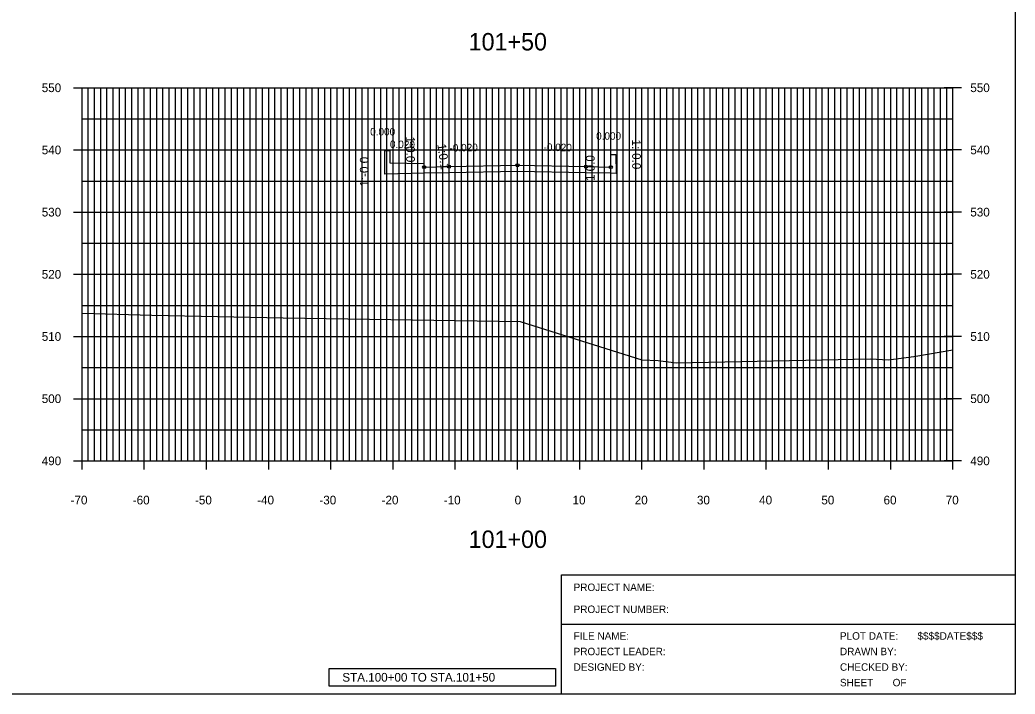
# Model space of a CAD drawing. Extents: x 1509063 to 1512863, y 401160 to 402918.
# Drawn here: x 1511262.7 to 1511422.7, y 402252.1 to 402360.5 of the extents above; entities that cross this region are included whole.
import ezdxf

# ---------------------------------------------------------------- set-up
doc = ezdxf.new("R2010")
doc.units = 0
for name, color, linetype in [('NBL1', 7, 'Continuous'), ('PET_P', 7, 'Continuous'), ('PRC', 7, 'Continuous'), ('PSP_P', 7, 'Continuous'), ('XAX_P', 7, 'Continuous'), ('XAXTIC_P', 7, 'Continuous'), ('XAXTXT_P_T', 7, 'Continuous'), ('XFRAME_P', 7, 'Continuous'), ('XGL_P', 7, 'Continuous'), ('XSL1_P', 7, 'Continuous'), ('XSL1_P_T', 7, 'Continuous'), ('XSL3_P', 7, 'Continuous'), ('XSLOG', 7, 'Continuous')]:
    doc.layers.add(name, color=color, linetype=linetype)

msp = doc.modelspace()

# ---------------------------------------------------------------- linework, layer by layer
at = {"layer": 'NBL1'}
for p, q in [((1511349.81, 402271.25), (1511422.73, 402271.25)), ((1511349.81, 402252.08), (1511349.81, 402271.25)), ((1511349.81, 402263.33), (1511422.73, 402263.33))]:
    msp.add_line(p, q, dxfattribs=at)
msp.add_lwpolyline([(1511422.73, 402252.08), (1511102.73, 402252.08), (1511102.73, 402462.08), (1511422.73, 402462.08)], close=True, dxfattribs=at)
at = {"layer": 'PET_P'}
for centre in [(1511331.73, 402336.9), (1511353.73, 402336.9)]:
    msp.add_circle(centre, 0.25, dxfattribs=at)
at = {"layer": 'PRC'}
msp.add_circle((1511342.73, 402337.12), 0.25, dxfattribs=at)
at = {"layer": 'PSP_P'}
for centre in [(1511327.73, 402336.82), (1511357.73, 402336.82)]:
    msp.add_circle(centre, 0.25, dxfattribs=at)
at = {"layer": 'XAX_P'}
for p, q in [((1511272.73, 402289.58), (1511272.73, 402349.58)), ((1511342.73, 402289.58), (1511342.73, 402349.58)), ((1511412.73, 402289.58), (1511412.73, 402349.58)), ((1511272.73, 402289.58), (1511412.73, 402289.58))]:
    msp.add_line(p, q, dxfattribs=at)
at = {"layer": 'XAXTIC_P'}
for p, q in [((1511271.33, 402349.58), (1511274.13, 402349.58)), ((1511341.33, 402349.58), (1511344.13, 402349.58)), ((1511414.13, 402349.58), (1511411.33, 402349.58)), ((1511271.33, 402339.58), (1511274.13, 402339.58)), ((1511341.33, 402339.58), (1511344.13, 402339.58)), ((1511414.13, 402339.58), (1511411.33, 402339.58)), ((1511271.33, 402329.58), (1511274.13, 402329.58)), ((1511341.33, 402329.58), (1511344.13, 402329.58)), ((1511414.13, 402329.58), (1511411.33, 402329.58)), ((1511271.33, 402319.58), (1511274.13, 402319.58)), ((1511341.33, 402319.58), (1511344.13, 402319.58)), ((1511414.13, 402319.58), (1511411.33, 402319.58)), ((1511271.33, 402309.58), (1511274.13, 402309.58)), ((1511341.33, 402309.58), (1511344.13, 402309.58)), ((1511414.13, 402309.58), (1511411.33, 402309.58)), ((1511271.33, 402299.58), (1511274.13, 402299.58)), ((1511341.33, 402299.58), (1511344.13, 402299.58)), ((1511414.13, 402299.58), (1511411.33, 402299.58)), ((1511272.73, 402288.18), (1511272.73, 402290.98)), ((1511282.73, 402288.18), (1511282.73, 402290.98)), ((1511292.73, 402288.18), (1511292.73, 402290.98)), ((1511302.73, 402288.18), (1511302.73, 402290.98)), ((1511312.73, 402288.18), (1511312.73, 402290.98)), ((1511322.73, 402288.18), (1511322.73, 402290.98)), ((1511332.73, 402288.18), (1511332.73, 402290.98)), ((1511342.73, 402288.18), (1511342.73, 402290.98)), ((1511352.73, 402288.18), (1511352.73, 402290.98)), ((1511362.73, 402288.18), (1511362.73, 402290.98)), ((1511372.73, 402288.18), (1511372.73, 402290.98)), ((1511382.73, 402288.18), (1511382.73, 402290.98)), ((1511392.73, 402288.18), (1511392.73, 402290.98)), ((1511402.73, 402288.18), (1511402.73, 402290.98)), ((1511412.73, 402288.18), (1511412.73, 402290.98)), ((1511271.33, 402289.58), (1511274.13, 402289.58)), ((1511341.33, 402289.58), (1511344.13, 402289.58)), ((1511414.13, 402289.58), (1511411.33, 402289.58))]:
    msp.add_line(p, q, dxfattribs=at)
at = {"layer": 'XFRAME_P'}
msp.add_lwpolyline([(1511312.43, 402256.18), (1511348.83, 402256.18), (1511348.83, 402253.38), (1511312.43, 402253.38)], close=True, dxfattribs=at)
at = {"layer": 'XGL_P'}
for p, q in [((1511272.73, 402349.58), (1511412.73, 402349.58)), ((1511272.73, 402289.58), (1511272.73, 402349.58)), ((1511273.73, 402289.58), (1511273.73, 402349.58)), ((1511274.73, 402289.58), (1511274.73, 402349.58)), ((1511275.73, 402289.58), (1511275.73, 402349.58)), ((1511276.73, 402289.58), (1511276.73, 402349.58)), ((1511277.73, 402289.58), (1511277.73, 402349.58)), ((1511278.73, 402289.58), (1511278.73, 402349.58)), ((1511279.73, 402289.58), (1511279.73, 402349.58)), ((1511280.73, 402289.58), (1511280.73, 402349.58)), ((1511281.73, 402289.58), (1511281.73, 402349.58)), ((1511282.73, 402289.58), (1511282.73, 402349.58)), ((1511283.73, 402289.58), (1511283.73, 402349.58)), ((1511284.73, 402289.58), (1511284.73, 402349.58)), ((1511285.73, 402289.58), (1511285.73, 402349.58)), ((1511286.73, 402289.58), (1511286.73, 402349.58)), ((1511287.73, 402289.58), (1511287.73, 402349.58)), ((1511288.73, 402289.58), (1511288.73, 402349.58)), ((1511289.73, 402289.58), (1511289.73, 402349.58)), ((1511290.73, 402289.58), (1511290.73, 402349.58)), ((1511291.73, 402289.58), (1511291.73, 402349.58)), ((1511292.73, 402289.58), (1511292.73, 402349.58)), ((1511293.73, 402289.58), (1511293.73, 402349.58)), ((1511294.73, 402289.58), (1511294.73, 402349.58)), ((1511295.73, 402289.58), (1511295.73, 402349.58)), ((1511296.73, 402289.58), (1511296.73, 402349.58)), ((1511297.73, 402289.58), (1511297.73, 402349.58)), ((1511298.73, 402289.58), (1511298.73, 402349.58)), ((1511299.73, 402289.58), (1511299.73, 402349.58)), ((1511300.73, 402289.58), (1511300.73, 402349.58)), ((1511301.73, 402289.58), (1511301.73, 402349.58)), ((1511302.73, 402289.58), (1511302.73, 402349.58)), ((1511303.73, 402289.58), (1511303.73, 402349.58)), ((1511304.73, 402289.58), (1511304.73, 402349.58)), ((1511305.73, 402289.58), (1511305.73, 402349.58)), ((1511306.73, 402289.58), (1511306.73, 402349.58)), ((1511307.73, 402289.58), (1511307.73, 402349.58)), ((1511308.73, 402289.58), (1511308.73, 402349.58)), ((1511309.73, 402289.58), (1511309.73, 402349.58)), ((1511310.73, 402289.58), (1511310.73, 402349.58)), ((1511311.73, 402289.58), (1511311.73, 402349.58)), ((1511312.73, 402289.58), (1511312.73, 402349.58)), ((1511313.73, 402289.58), (1511313.73, 402349.58)), ((1511314.73, 402289.58), (1511314.73, 402349.58)), ((1511315.73, 402289.58), (1511315.73, 402349.58)), ((1511316.73, 402289.58), (1511316.73, 402349.58)), ((1511317.73, 402289.58), (1511317.73, 402349.58)), ((1511318.73, 402289.58), (1511318.73, 402349.58)), ((1511319.73, 402289.58), (1511319.73, 402349.58)), ((1511320.73, 402289.58), (1511320.73, 402349.58)), ((1511321.73, 402289.58), (1511321.73, 402349.58)), ((1511322.73, 402289.58), (1511322.73, 402349.58)), ((1511323.73, 402289.58), (1511323.73, 402349.58)), ((1511324.73, 402289.58), (1511324.73, 402349.58)), ((1511325.73, 402289.58), (1511325.73, 402349.58)), ((1511326.73, 402289.58), (1511326.73, 402349.58)), ((1511327.73, 402289.58), (1511327.73, 402349.58)), ((1511328.73, 402289.58), (1511328.73, 402349.58)), ((1511329.73, 402289.58), (1511329.73, 402349.58)), ((1511330.73, 402289.58), (1511330.73, 402349.58)), ((1511331.73, 402289.58), (1511331.73, 402349.58)), ((1511332.73, 402289.58), (1511332.73, 402349.58)), ((1511333.73, 402289.58), (1511333.73, 402349.58)), ((1511334.73, 402289.58), (1511334.73, 402349.58)), ((1511335.73, 402289.58), (1511335.73, 402349.58)), ((1511336.73, 402289.58), (1511336.73, 402349.58)), ((1511337.73, 402289.58), (1511337.73, 402349.58)), ((1511338.73, 402289.58), (1511338.73, 402349.58)), ((1511339.73, 402289.58), (1511339.73, 402349.58)), ((1511340.73, 402289.58), (1511340.73, 402349.58)), ((1511341.73, 402289.58), (1511341.73, 402349.58)), ((1511342.73, 402289.58), (1511342.73, 402349.58)), ((1511343.73, 402289.58), (1511343.73, 402349.58)), ((1511344.73, 402289.58), (1511344.73, 402349.58)), ((1511345.73, 402289.58), (1511345.73, 402349.58)), ((1511346.73, 402289.58), (1511346.73, 402349.58)), ((1511347.73, 402289.58), (1511347.73, 402349.58)), ((1511348.73, 402289.58), (1511348.73, 402349.58)), ((1511349.73, 402289.58), (1511349.73, 402349.58)), ((1511350.73, 402289.58), (1511350.73, 402349.58)), ((1511351.73, 402289.58), (1511351.73, 402349.58)), ((1511352.73, 402289.58), (1511352.73, 402349.58)), ((1511353.73, 402289.58), (1511353.73, 402349.58)), ((1511354.73, 402289.58), (1511354.73, 402349.58)), ((1511355.73, 402289.58), (1511355.73, 402349.58)), ((1511356.73, 402289.58), (1511356.73, 402349.58)), ((1511357.73, 402289.58), (1511357.73, 402349.58)), ((1511358.73, 402289.58), (1511358.73, 402349.58)), ((1511359.73, 402289.58), (1511359.73, 402349.58)), ((1511360.73, 402289.58), (1511360.73, 402349.58)), ((1511361.73, 402289.58), (1511361.73, 402349.58)), ((1511362.73, 402289.58), (1511362.73, 402349.58)), ((1511363.73, 402289.58), (1511363.73, 402349.58)), ((1511364.73, 402289.58), (1511364.73, 402349.58)), ((1511365.73, 402289.58), (1511365.73, 402349.58)), ((1511366.73, 402289.58), (1511366.73, 402349.58)), ((1511367.73, 402289.58), (1511367.73, 402349.58)), ((1511368.73, 402289.58), (1511368.73, 402349.58)), ((1511369.73, 402289.58), (1511369.73, 402349.58)), ((1511370.73, 402289.58), (1511370.73, 402349.58)), ((1511371.73, 402289.58), (1511371.73, 402349.58)), ((1511372.73, 402289.58), (1511372.73, 402349.58)), ((1511373.73, 402289.58), (1511373.73, 402349.58)), ((1511374.73, 402289.58), (1511374.73, 402349.58)), ((1511375.73, 402289.58), (1511375.73, 402349.58)), ((1511376.73, 402289.58), (1511376.73, 402349.58)), ((1511377.73, 402289.58), (1511377.73, 402349.58)), ((1511378.73, 402289.58), (1511378.73, 402349.58)), ((1511379.73, 402289.58), (1511379.73, 402349.58)), ((1511380.73, 402289.58), (1511380.73, 402349.58)), ((1511381.73, 402289.58), (1511381.73, 402349.58)), ((1511382.73, 402289.58), (1511382.73, 402349.58)), ((1511383.73, 402289.58), (1511383.73, 402349.58)), ((1511384.73, 402289.58), (1511384.73, 402349.58)), ((1511385.73, 402289.58), (1511385.73, 402349.58)), ((1511386.73, 402289.58), (1511386.73, 402349.58)), ((1511387.73, 402289.58), (1511387.73, 402349.58)), ((1511388.73, 402289.58), (1511388.73, 402349.58)), ((1511389.73, 402289.58), (1511389.73, 402349.58)), ((1511390.73, 402289.58), (1511390.73, 402349.58)), ((1511391.73, 402289.58), (1511391.73, 402349.58)), ((1511392.73, 402289.58), (1511392.73, 402349.58)), ((1511393.73, 402289.58), (1511393.73, 402349.58)), ((1511394.73, 402289.58), (1511394.73, 402349.58)), ((1511395.73, 402289.58), (1511395.73, 402349.58)), ((1511396.73, 402289.58), (1511396.73, 402349.58)), ((1511397.73, 402289.58), (1511397.73, 402349.58)), ((1511398.73, 402289.58), (1511398.73, 402349.58)), ((1511399.73, 402289.58), (1511399.73, 402349.58)), ((1511400.73, 402289.58), (1511400.73, 402349.58)), ((1511401.73, 402289.58), (1511401.73, 402349.58)), ((1511402.73, 402289.58), (1511402.73, 402349.58)), ((1511403.73, 402289.58), (1511403.73, 402349.58)), ((1511404.73, 402289.58), (1511404.73, 402349.58)), ((1511405.73, 402289.58), (1511405.73, 402349.58)), ((1511406.73, 402289.58), (1511406.73, 402349.58)), ((1511407.73, 402289.58), (1511407.73, 402349.58)), ((1511408.73, 402289.58), (1511408.73, 402349.58)), ((1511409.73, 402289.58), (1511409.73, 402349.58)), ((1511410.73, 402289.58), (1511410.73, 402349.58)), ((1511411.73, 402289.58), (1511411.73, 402349.58)), ((1511412.73, 402289.58), (1511412.73, 402349.58)), ((1511272.73, 402344.58), (1511412.73, 402344.58)), ((1511272.73, 402339.58), (1511412.73, 402339.58)), ((1511272.73, 402334.58), (1511412.73, 402334.58)), ((1511272.73, 402329.58), (1511412.73, 402329.58)), ((1511272.73, 402324.58), (1511412.73, 402324.58)), ((1511272.73, 402319.58), (1511412.73, 402319.58)), ((1511272.73, 402314.58), (1511412.73, 402314.58)), ((1511272.73, 402309.58), (1511412.73, 402309.58)), ((1511272.73, 402304.58), (1511412.73, 402304.58)), ((1511272.73, 402299.58), (1511412.73, 402299.58)), ((1511272.73, 402294.58), (1511412.73, 402294.58)), ((1511272.73, 402289.58), (1511412.73, 402289.58))]:
    msp.add_line(p, q, dxfattribs=at)
at = {"layer": 'XSL1_P'}
msp.add_lwpolyline([(1511321.39, 402335.69), (1511321.4, 402339.51), (1511322.23, 402339.51), (1511322.23, 402337.51), (1511327.65, 402337.4), (1511327.73, 402336.82), (1511331.73, 402336.9), (1511342.73, 402337.12), (1511353.73, 402336.9), (1511357.73, 402336.82), (1511357.73, 402338.82), (1511358.56, 402338.82), (1511358.57, 402335.8)], dxfattribs=at)
at = {"layer": 'XSL3_P'}
msp.add_lwpolyline([(1511331.73, 402335.9), (1511327.73, 402335.82), (1511321.39, 402335.69), (1511321.4, 402339.51), (1511322.23, 402339.51), (1511322.23, 402337.51), (1511327.65, 402337.4), (1511327.73, 402336.82), (1511331.73, 402336.9), (1511342.72, 402337.12), (1511353.73, 402336.9), (1511357.73, 402336.82), (1511357.73, 402338.82), (1511358.56, 402338.82), (1511358.57, 402335.8), (1511357.73, 402335.82), (1511353.73, 402335.9), (1511342.72, 402336.12)], close=True, dxfattribs=at)
at = {"layer": 'XSLOG'}
msp.add_lwpolyline([(1511272.73, 402313.33), (1511283.95, 402313.02), (1511305.07, 402312.56), (1511343.14, 402311.99), (1511362.7, 402305.85), (1511365.34, 402305.73), (1511368.26, 402305.34), (1511399.5, 402305.98), (1511402.38, 402305.82), (1511406.47, 402306.39), (1511412.73, 402307.42)], dxfattribs=at)

# ---------------------------------------------------------------- texts
at = {"layer": 'NBL1'}
for s, p in [('PROJECT NAME:', (1511351.75, 402268.65)), ('PROJECT NUMBER:', (1511351.75, 402265.12)), ('FILE NAME:', (1511351.75, 402260.83)), ('PLOT DATE:', (1511394.57, 402260.83)), ('$$$$DATE$$$', (1511407.03, 402260.83)), ('PROJECT LEADER:', (1511351.75, 402258.33)), ('DRAWN BY:', (1511394.57, 402258.33)), ('DESIGNED BY:', (1511351.75, 402255.83)), ('CHECKED BY:', (1511394.57, 402255.83)), ('SHEET       OF', (1511394.57, 402253.33))]:
    msp.add_text(s, height=1.2, rotation=360, dxfattribs=at).set_placement(p)
at = {"layer": 'XAXTXT_P_T'}
for s, height, p in [('101+50', 2.8, (1511334.87, 402355.58)), ('550', 1.4, (1511266.24, 402348.88)), ('550', 1.4, (1511415.53, 402348.88)), ('540', 1.4, (1511266.24, 402338.88)), ('540', 1.4, (1511415.53, 402338.88)), ('530', 1.4, (1511266.24, 402328.88)), ('530', 1.4, (1511415.53, 402328.88)), ('520', 1.4, (1511266.24, 402318.88)), ('520', 1.4, (1511415.53, 402318.88)), ('510', 1.4, (1511266.24, 402308.88)), ('510', 1.4, (1511415.53, 402308.88)), ('500', 1.4, (1511266.24, 402298.88)), ('500', 1.4, (1511415.53, 402298.88)), ('490', 1.4, (1511266.24, 402288.88)), ('490', 1.4, (1511415.53, 402288.88)), ('-70', 1.4, (1511270.88, 402282.58)), ('-60', 1.4, (1511280.88, 402282.58)), ('-50', 1.4, (1511290.88, 402282.58)), ('-40', 1.4, (1511300.88, 402282.58)), ('-30', 1.4, (1511310.88, 402282.58)), ('-20', 1.4, (1511320.88, 402282.58)), ('-10', 1.4, (1511330.88, 402282.58)), ('0', 1.4, (1511342.27, 402282.58)), ('10', 1.4, (1511351.58, 402282.58)), ('20', 1.4, (1511361.58, 402282.58)), ('30', 1.4, (1511371.58, 402282.58)), ('40', 1.4, (1511381.58, 402282.58)), ('50', 1.4, (1511391.58, 402282.58)), ('60', 1.4, (1511401.58, 402282.58)), ('70', 1.4, (1511411.58, 402282.58)), ('101+00', 2.8, (1511334.87, 402275.58))]:
    msp.add_text(s, height=height, dxfattribs=at).set_placement(p)
at = {"layer": 'XFRAME_P'}
msp.add_text('STA.100+00 TO STA.101+50', height=1.4, dxfattribs=at).set_placement((1511314.57, 402254.08))
at = {"layer": 'XSL1_P_T'}
for s, height, rotation, p in [('0.000', 1.2, 360, (1511319.04, 402341.91)), ('0.000', 1.2, 360, (1511319.04, 402341.91)), ('0.000', 1.2, 360, (1511355.37, 402341.22)), ('0.000', 1.2, 360, (1511355.37, 402341.22)), ('0.020', 1.2, 358.8542, (1511322.21, 402339.91)), ('0.020', 1.2, 358.8542, (1511322.21, 402339.91)), ('1:0.0', 1.4, 270.0286, (1511324.83, 402341.75)), ('1:0.0', 1.4, 270.0286, (1511324.83, 402341.75)), ('1:-0.0', 1.4, 270.1899, (1511361.15, 402341.25)), ('1:-0.0', 1.4, 270.1899, (1511361.15, 402341.25)), ('1:0.1', 1.4, 278.1301, (1511329.83, 402340.46)), ('1:0.1', 1.4, 278.1301, (1511329.83, 402340.46)), ('-0.020', 1.2, 1.1458, (1511331.81, 402339.3)), ('-0.020', 1.2, 1.1458, (1511331.81, 402339.3)), ('-0.020', 1.2, 1.1458, (1511331.81, 402339.3)), ('-0.020', 1.2, 358.8542, (1511346.91, 402339.44)), ('-0.020', 1.2, 358.8542, (1511346.91, 402339.44)), ('-0.020', 1.2, 358.8542, (1511346.91, 402339.44)), ('1:-0.0', 1.4, 89.85, (1511318.78, 402333.68)), ('1:-0.0', 1.4, 89.85, (1511318.78, 402333.68)), ('1:0.0', 1.4, 89.9714, (1511355.13, 402334.58)), ('1:0.0', 1.4, 89.9714, (1511355.13, 402334.58))]:
    msp.add_text(s, height=height, rotation=rotation, dxfattribs=at).set_placement(p)

doc.saveas('drawing.dxf')
